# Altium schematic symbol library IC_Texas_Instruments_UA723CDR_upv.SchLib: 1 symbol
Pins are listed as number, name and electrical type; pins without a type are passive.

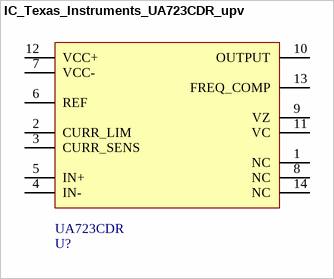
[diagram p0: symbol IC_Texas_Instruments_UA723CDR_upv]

## IC_Texas_Instruments_UA723CDR_upv
designator U?  Part Number: UA723CDR
IC Linear Voltage Regulator IC Positive Adjustable 1 Output 2 V ~ 37 V 150mA 14-SOIC; Manufacturer: Texas Instruments; Voltage: 40V
footprint Texas_Instruments_D_R-PDSO-G14_0
pins: 1 NC, 2 CURR_LIM, 3 CURR_SENS, 4 IN-, 5 IN+, 6 REF, 7 VCC-, 8 NC, 9 VZ, 10 OUTPUT, 11 VC, 12 VCC+, 13 FREQ_COMP, 14 NC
